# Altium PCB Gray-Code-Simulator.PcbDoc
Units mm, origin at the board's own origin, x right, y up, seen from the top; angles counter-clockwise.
Board outline 51 x 32.5 mm, 2 copper layers (Top Layer, Bottom Layer), stack 1.601 mm thick; 30 components, 13 nets, 62 pads, 0 vias.
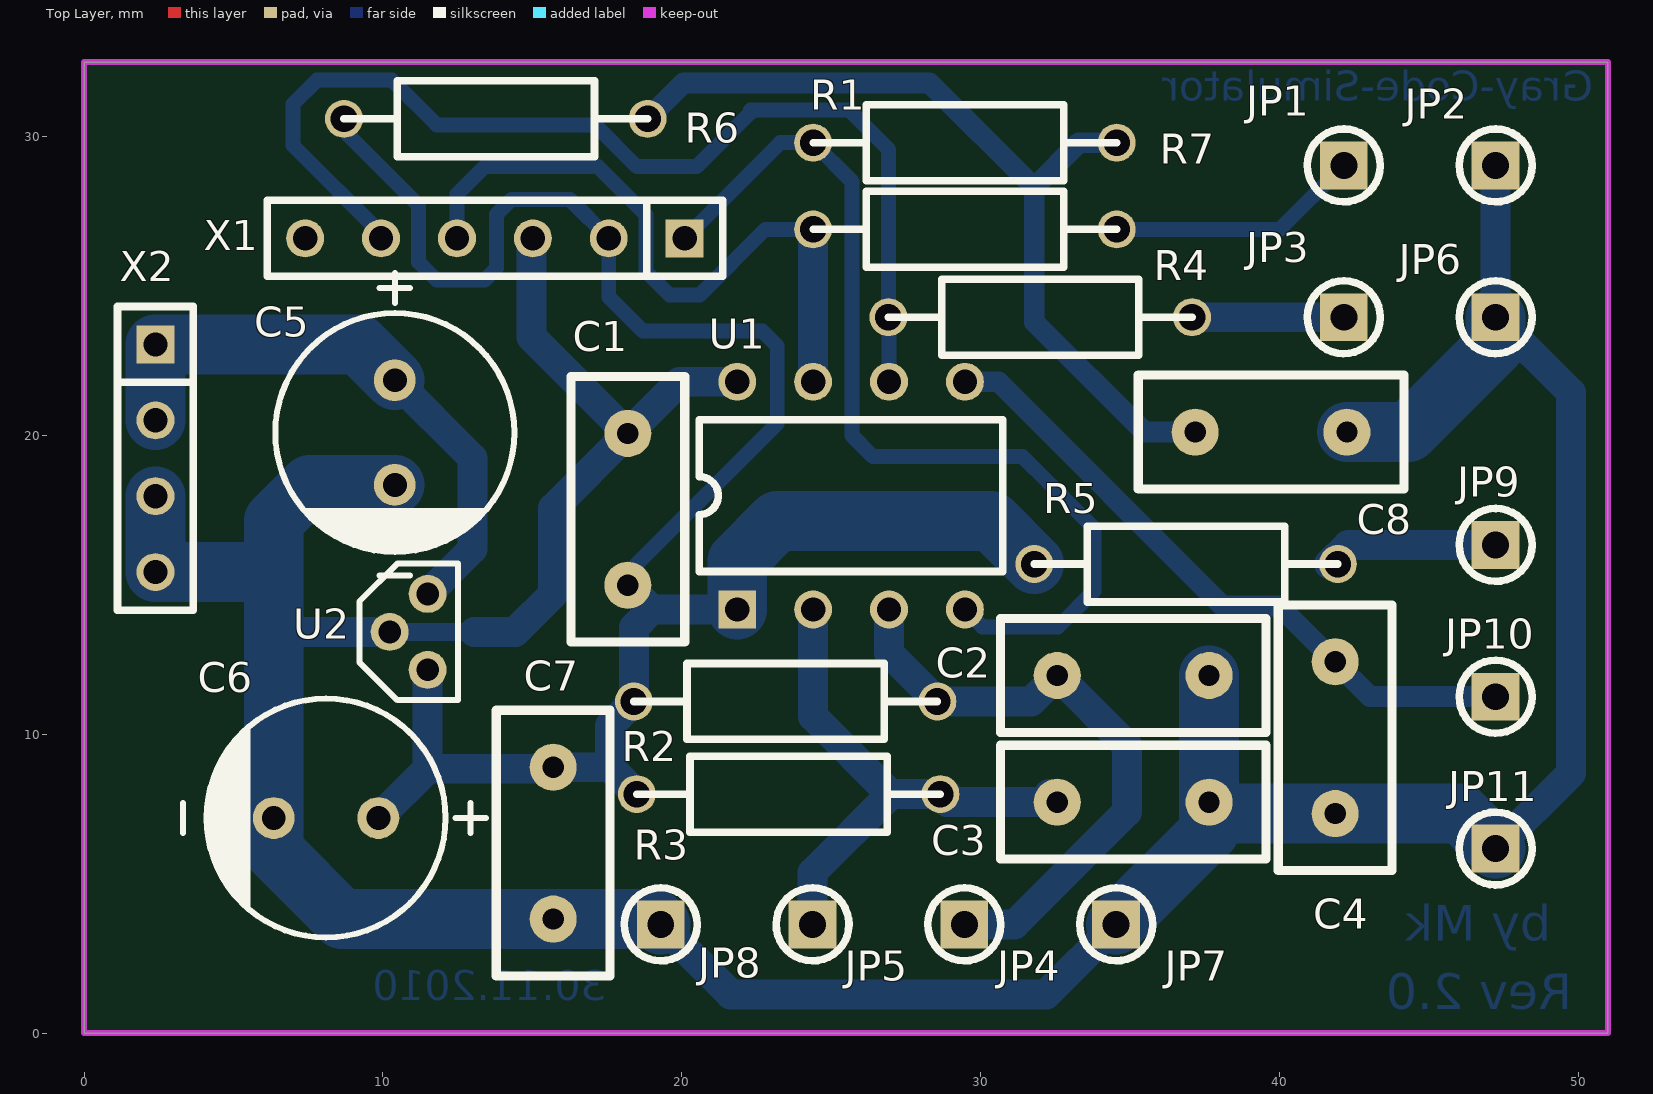
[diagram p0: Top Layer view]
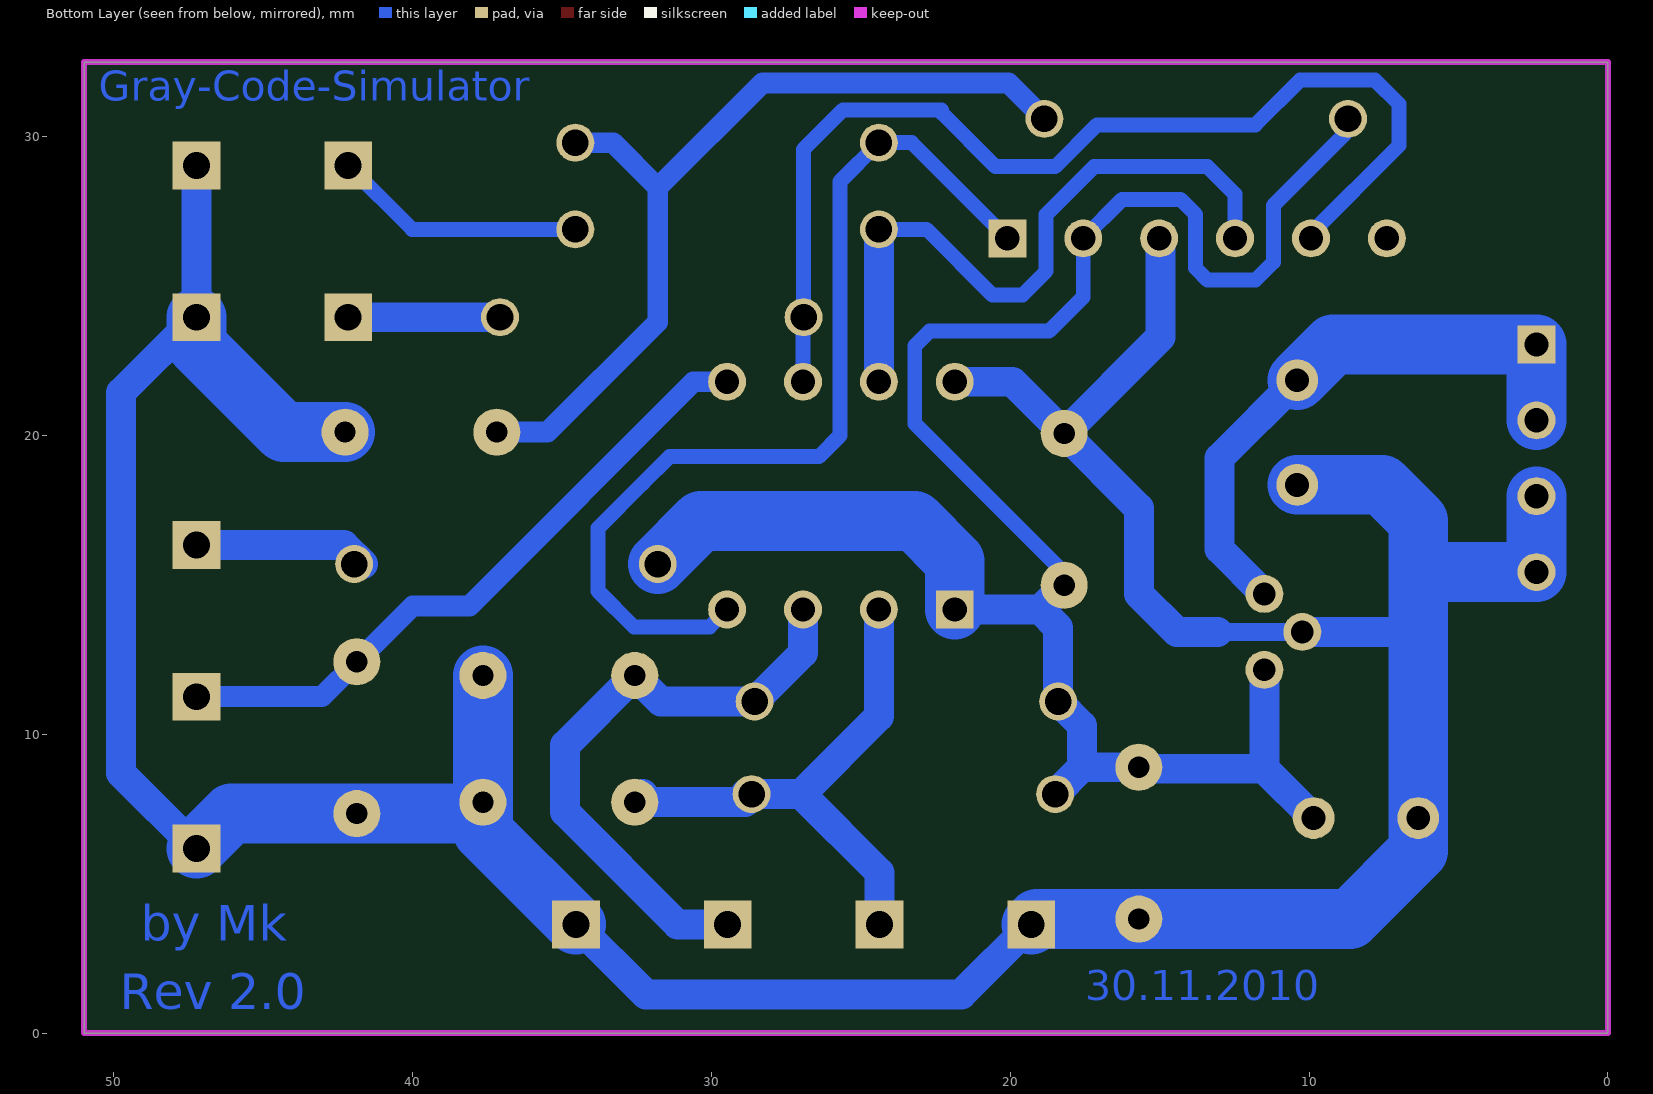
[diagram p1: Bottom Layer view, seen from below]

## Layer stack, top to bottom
Top Layer: signal copper 0.0356
Dielectric: core 1.53, FR-4, Dk 4.8
Bottom Layer: signal copper 0.0356

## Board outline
0,0 51,0 51,32.5 0,32.5

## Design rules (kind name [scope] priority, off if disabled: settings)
Clearance [All] p1: gap=0.2
ComponentClearance [All] p1 off: gap=0.254 collisioncheckmode=3 verticalgap=0.254 showdistances=FALSE
HoleSize [All] p1: absolutevalues=TRUE maxlimit=4 minlimit=0.025 maxpercent=80.000 minpercent=20.000
PlaneConnect [All] p1: planeconnectstyle=Relief reliefexpansion=0.5 reliefentries=4 reliefconductorwidth=0.2 reliefairgap=0.2
PolygonConnect [All] p1: connectstyle=Direct reliefconductorwidth=1 reliefentries=4 polygonreliefangle="90 Angle"
RoutingVias [All] p1: holewidth=0.5 width=0.9 viastyle="Through Hole" minholewidth=0.4 minwidth=0.8 maxholewidth=0.711 maxwidth=1.27
SolderMaskExpansion [All] p1: expansion=0.102
TestPointUsage [All] p1: valid=0 allowmultiple=FALSE
Testpoint [All] p1: side=15 testpointundercomponent=TRUE minsize=1.016 maxsize=2.54 preferedsize=1.524 minholesize=0 maxholesize=1.016 preferedholesize=0.813 testpointgrid=0.025 style=1023 order=0123456789
Width [All] p1: maxlimit=10 minlimit=0.2 preferedwidth=0.5
16 further rules are at their usual default settings.

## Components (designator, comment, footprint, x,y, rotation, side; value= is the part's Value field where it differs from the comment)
C1 "100nF" RAD0.2 18.2,20.07 r270 top
C2 "100nF" RAD0.2 32.57,11.97 r0 top
C3 "100nF" RAD0.2 32.57,7.73 r0 top
C4 "100nF" RAD0.2 41.87,12.43 r270 top
C5 "330uF" ELK_RM035_8x11.5 10.4,20.1 r270 top
C6 "330uF" ELK_RM035_8x11.5 8.1,7.2 r180 top
C7 "100nF" RAD0.2 15.7,8.9 r270 top
C8 "100nF" RAD0.2 37.184,20.116 r0 top
JP1 "Jumper" SIP1 42.16,29.04 r0 top
JP2 "Jumper" SIP1 47.24,29.04 r0 top
JP3 "Jumper" SIP1 42.16,23.96 r0 top
JP4 "Jumper" SIP1 29.46,3.64 r0 top
JP5 "Jumper" SIP1 24.38,3.64 r0 top
JP6 "Jumper" SIP1 47.24,23.96 r0 top
JP7 "Jumper" SIP1 34.54,3.64 r0 top
JP8 "Jumper" SIP1 19.3,3.64 r0 top
JP9 "Jumper" SIP1 47.24,16.34 r0 top
JP10 "Jumper" SIP1 47.24,11.26 r90 top
JP11 "Jumper" SIP1 47.24,6.18 r90 top
R1 "470R" R0207 24.4,26.9 r0 top
R2 "10K" R0207 18.4,11.1 r0 top
R3 "10K" R0207 18.5,8 r0 top
R4 "470R" R0207 26.92,23.96 r0 top
R5 "10K" R0207 31.8,15.7 r0 top
R6 "10K" R0207 8.7,30.6 r0 top
R7 "470R" R0207 24.4,29.8 r0 top
U1 "PIC12F683" DIP8 21.86,14.18 r90 top
U2 "L78M05CDT" TO-92A 11.5,14.7 r270 top
X1 "SIP6" SIP6 20.1,26.6 r180 top
X2 "SIP6" SIP4 2.39,23.05 r270 top

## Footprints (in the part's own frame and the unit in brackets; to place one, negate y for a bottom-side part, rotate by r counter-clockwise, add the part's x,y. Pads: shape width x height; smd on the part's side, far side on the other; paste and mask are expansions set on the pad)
DIP8 [mil]
  rect 50x50 hole 32: 1(0,0)
  round 50 hole 32: 2(0,-100) 3(0,-200) 4(0,-300) 5(300,-300) 6(300,-200) 7(300,-100) 8(300,0)
  silkscreen extent 50,-350 250,50
ELK_RM035_8x11.5 [mm]
  round 1.4 hole 0.8: 1(-1.75,0) 2(1.75,0)
  silkscreen extent -5.35,-4 4.79,4
R0207 [mil]
  round 50 hole 35: 1(0,0) 2(400,0)
  silkscreen extent 0,-50 400,50
RAD0.2 [mil]
  round 62 hole 28: 1(0,0) 2(200,0)
  silkscreen extent -75,-75 275,75
SIP1 [mm]
  rect 1.6x1.6 hole 0.9: 1(0,0)
  silkscreen extent -1.22,-1.22 1.22,1.22
SIP4 [mil]
  rect 50x50 hole 32: 1(0,0)
  round 50 hole 32: 2(100,0) 3(200,0) 4(300,0)
  silkscreen extent -50,-50 350,50
SIP6 [mil]
  rect 50x50 hole 32: 1(0,0)
  round 50 hole 32: 2(100,0) 3(200,0) 4(300,0) 5(400,0) 6(500,0)
  silkscreen extent -50,-50 550,50
TO-92A [mil]
  round 50 hole 30: 1(0,0) 2(50,-50) 3(100,0)
  silkscreen extent -40,-90 140,40

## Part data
C1 C2 C3 C4 C7 C8: library part 100NF_RM05, "Capacitor"
C5 C6: library part 330UF_RM3.5_16V, "Capacitor Aluminum Electrolytic 330UF, 16V 105°C , Low Impedance"
JP1 JP2 JP3 JP4 JP5 JP6 JP7 JP8 JP9 JP10 JP11: library part JUMPER1, "Lötauge"
R1 R2 R3 R4 R5 R6 R7: library part DUMMY_RM1016, "Resistor Axial"
U1: library part PIC12C508-04_SO-8, "8-BIT CMOS Microcontroller, 8-PIN,"
U2: library part 78M05_TO252, "Voltage Regulators 5V SMD"
X1: "Stiftleiste, 6-Pin"
X2: library part SIP4, "Stiftleiste, 4-Pin"

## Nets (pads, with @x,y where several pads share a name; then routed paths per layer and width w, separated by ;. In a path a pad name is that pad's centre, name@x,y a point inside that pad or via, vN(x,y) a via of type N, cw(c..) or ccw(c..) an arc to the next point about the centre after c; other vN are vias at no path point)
GND: C1.1 C2.2 C3.2 C4.2 C5.2 C6.2 C7.2 C8.2 JP2.1 JP6.1 JP7.1 JP8.1 JP11.1 U1.8 U2.2 X1.3 X2.3 X2.4 | length 134.2
  Bottom Layer w0.6: U2.2 13.06,13.43 13.53,13.43
  Bottom Layer w1: 6.35,13.43 U2.2 ; 13.06,13.43 13.53,13.43 14.43,13.43 15.7,14.7 15.7,17.03 15.7,17.57 C1.1 ; X1.3 14.98,26.56 14.98,23.29 C1.1 ; JP8.1 21.64,1.3 32.2,1.3 JP7.1 ; U1.8 19.93,21.8 C1.1 ; JP11.1 49.76,8.7 49.76,21.44 JP6.1 JP2.1
  Bottom Layer w2: X2.3 X2.4 6.28,15.43 6.35,15.5 ; C5.2 7.55,18.35 6.35,17.15 6.35,15.5 ; JP8.1 19.12,3.82 C7.2 8.63,3.82 6.35,6.1 C6.2 6.35,13.43 6.35,15.5 ; JP7.1 37.65,6.75 C3.2 ; C2.2 37.65,11.55 C3.2 ; C8.2 44.316,20.116 47.24,23.04 JP6.1 ; JP11.1 46.07,7.35 C4.2 38.03,7.35 C3.2
ISCPCLK: R4.1 U1.6 X1.5 | length 36.4
  Bottom Layer w0.5: X1.5 9.94,26.76 7,29.7 7,31.1 7.8,31.9 10.3,31.9 11.8,30.4 17.1,30.4 18.5,29 20.5,29 22.3,30.8 22.3,30.9 25.6,30.9 26.92,29.58 R4.1 26.94,23.98 26.94,21.82 U1.6 U1.6@26.92,21.82
  Bottom Layer w1: U1.6 U1.6@26.94,21.82
ISCPDAT: R1.1 U1.7 X1.4 | length 22.9
  Bottom Layer w0.5: X1.4 12.48,28.08 13.4,29 17.2,29 18.8,27.4 18.8,25.5 19.6,24.7 20.6,24.7 22.8,26.9 R1.1 R1.1@24.4,27.1
  Bottom Layer w1: U1.7 R1.1
MCLR: R7.1 U1.4 X1.1 | length 32.5
  Bottom Layer w0.5: X1.1 23.3,29.8 R7.1 25.7,28.5 25.7,20 26.4,19.3 31.4,19.3 32.3,18.4 33.8,16.9 33.8,14.8 32.6,13.6 30.06,13.6 U1.4
NetC4_1: C4.1 JP10.1 U1.5 | length 22.2
  Bottom Layer w0.7: U1.5@29.48,21.88 U1.5 30.6,21.8 38.1,14.3 40,14.3 C4.1 43.04,11.26 JP10.1
NetC8_1: C8.1 R6.2 R7.2 | length 29.7
  Bottom Layer w0.7: R6.2 20.06,31.8 28.3,31.8 31.8,28.3 ; R7.2 33.3,29.8 31.8,28.3 ; C8.1 35.484,20.116 31.8,23.8 31.8,28.3
NetJP1_1: JP1.1 R1.2 | length 8.5
  Bottom Layer w0.5: R1.2 40.02,26.9 JP1.1
NetJP3_1: JP3.1 R4.2 | length 5.1
  Bottom Layer w1: R4.2 JP3.1
NetJP9_1: JP9.1 R5.2 | length 5.8
  Bottom Layer w1: R5.2@41.66,15.7 42.3,16.34 JP9.1
T1: C3.1 JP5.1 R3.2 U1.2 | length 18.7
  Bottom Layer w1: JP5.1 24.38,5.38 27,8 ; U1.2 24.4,10.6 27,8 ; R3.2@28.87,7.73 C3.1 C3.1@32.3,8 ; R3.2@28.87,8 R3.2 27,8
T2: C2.1 JP4.1 R2.2 U1.3 | length 20.7
  Bottom Layer w1: U1.3 26.94,12.72 R2.2 31.7,11.1 C2.1 34.9,9.64 34.9,7.4 31.14,3.64 JP4.1
VCC-5V: C1.2 C6.1 C7.1 R2.1 R3.1 R5.1 R6.1 U1.1 U2.3 X1.2 | length 69
  Bottom Layer w0.5: R6.1@8.8,30.1 11.2,27.7 11.2,25.8 11.8,25.2 13.4,25.2 13.8,25.6 13.8,27.4 14.3,27.9 16.26,27.9 X1.2 17.56,24.64 18.7,23.5 22.7,23.5 23.2,23 23.2,20.4 18.2,15.4 C1.2
  Bottom Layer w1: C6.1 11.5,8.85 ; U2.3 11.5,8.85 ; C1.2 19.01,14.18 ; R3.1 17.6,8.9 ; U1.1@21.48,14.18 U1.1 19.01,14.18 ; 11.5,8.85 15.65,8.85 C7.1 17.6,8.9 ; 17.6,8.9 17.6,10.3 R2.1 18.4,13.57 19.01,14.18
  Bottom Layer w2: U1.1 21.86,15.8 23.203,17.143 30.357,17.143 R5.1
VCC-12V: C5.1 U2.1 X2.1 X2.2 | length 19.9
  Bottom Layer w1: C5.1 13,19.25 13,16.2 U2.1
  Bottom Layer w2: X2.2 X2.1 9.2,23.05 C5.1
pads on no net: X1.6

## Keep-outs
Keep-Out Layer:
  the board outline again, w0.2

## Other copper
Top Layer:
  text "2" at 135.638,-82.51 h1.27
  text "Top Layer" at 148.218,-82.61 h1.27
Bottom Layer:
  text "Gray-Code-Simulator" at 50.5,31.2 h1
  text "by Mk" at 49.1,3.1 h1.2
  text "30.11.2010" at 17.5,1.1 h1
  text "Rev 2.0" at 49.8,0.8 h1.2
  text "3" at 135.638,-82.51 h1.27
  text "Bottom Layer" at 148.218,-82.61 h1.27

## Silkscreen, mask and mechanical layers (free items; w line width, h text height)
Top Overlay:
  text "1" at 135.808,-82.5 h1.27
  text "Top Overlay" at 148.218,-82.61 h1.27
Bottom Overlay:
  text "4" at 135.638,-82.51 h1.27
  text "Bottom Overlay" at 148.218,-82.61 h1.27
Mechanical 16:
  lines w0.127: -109.36,-40.23 -104.28,-40.23 ; -109.36,8.03 -104.28,8.03 ; -109.36,56.29 -104.28,56.29 ; -39.36,-88.49 -39.36,-83.41 ; -39.36,99.47 -39.36,104.55 ; 30.64,-88.49 30.64,-83.41 ; 30.64,99.47 30.64,104.55 ; 100.64,-88.49 100.64,-83.41 ; 100.64,99.47 100.64,104.55 ; 165.56,-40.23 170.64,-40.23 ; 165.56,8.03 170.64,8.03 ; 165.56,56.29 170.64,56.29 ; -109.36,-88.49 -109.36,104.55 170.64,104.55 170.64,-88.49 -109.36,-88.49 ; -104.28,-83.41 165.56,-83.41 165.56,99.47 -104.28,99.47 -104.28,-83.41
  lines w0.2: 2.727,-83.211 2.727,-63.399 70.481,-63.422 ; 70.499,-83.41 70.499,-63.41 165.499,-63.41 ; 70.499,-80.41 147.499,-80.41 165.499,-80.41 ; 70.499,-77.41 127.499,-77.41 ; 70.499,-72.41 127.499,-72.41 ; 80.499,-77.41 80.499,-72.41 ; 112.455,-80.41 112.455,-72.41 ; 127.499,-83.41 127.499,-63.41 ; 147.499,-83.41 147.499,-63.41
  text "1" at -73.114,101.121 h1.78
  text "2" at -0.47,101.121 h1.78
  text "3" at 72.682,101.121 h1.78
  text "4" at 145.58,101.121 h1.78
  text "A" at -107.455,78.109 h1.78
  text "A" at 167.465,78.109 h1.78
  text "B" at -107.455,30.052 h1.78
  text "B" at 167.465,30.052 h1.78
  text "C" at -107.455,-18.462 h1.78
  text "C" at 167.465,-18.462 h1.78
  text "D" at -107.455,-66.468 h1.78
  text "D" at 167.465,-66.468 h1.78
  text "Copying of this document, and giving it to others and the use or comunication of the" at 3.921,-66.726 h1
  text "Gray-Code-Simulator" at 73.088,-68.59 h2.27
  text "contents therof, ar forbidden without express authority. Offenders are liable to the" at 3.921,-68.758 h1
  text "payment of damages. All rights are reserved in the event of the grant of a patent or" at 3.921,-70.79 h1
  text "the registration of a utility model or design." at 3.921,-72.822 h1
  text "by MK" at 149.64,-73.7 h3
  text "Weitergabe sowie vervielfaeltigung dieser Unterlage, Verwertung und Mitteilung ihres Inhalts" at 3.921,-75.362 h1
  text "Size:" at 71.199,-75.61 h1.27
  text "A4" at 76.499,-75.61 h1.27
  text "Number:" at 81.299,-75.61 h1.27
  text "Revision: 2.0" at 113.589,-75.61 h1.27
  text "1.0" at 92.4,-75.76 h1.27
  text "nicht gestattet, soweit nicht ausdruecklich zugestanden. Zuwiederhandlung verpflichtet zu" at 3.921,-77.394 h1
  text "Schadensersatz. Alle Rechte fuer den Fall der Patenterteilung oder Gebrauchsmuster-" at 3.921,-79.426 h1
  text ".Pcb_File_Name_No_Path" at 71.199,-79.51 h1.27
  text "Project: P_025" at 113.589,-79.674 h1.27
  text "Eintragungen vorbehalten." at 3.921,-81.458 h1
  text "Print Date:" at 96.1,-82.44 h1.27
  text "Date:" at 71.199,-82.51 h1.27
  text "30.11.2010" at 76.999,-82.51 h1.27
  text ".Print_Date" at 107.719,-82.51 h1.27
  text "Sheet    of 4" at 128.999,-82.51 h1.27
  text "1" at -73.114,-86.839 h1.78
  text "2" at -0.47,-86.839 h1.78
  text "3" at 72.682,-86.839 h1.78
  text "4" at 145.58,-86.839 h1.78

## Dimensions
0,0 to 51,0 on Mechanical 1
0,0 to 0,32.5 on Mechanical 1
